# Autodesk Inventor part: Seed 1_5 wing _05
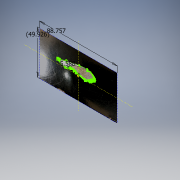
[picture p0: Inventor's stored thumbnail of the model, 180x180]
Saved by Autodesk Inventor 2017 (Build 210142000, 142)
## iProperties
Created: 2017-01
Part Number: Seed 1_5 wing _05
Material: Generic
Document SubType Name: Modeling
Designer: Brock Davis
Density: 1 g/cm^3
Appearance: Default
Author: Brock Davis
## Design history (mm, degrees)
sketch "Sketch1"
  geometry: L1 (-44.378, 24.963)-(44.378, 24.963); L2 (44.378, 24.963)-(44.378, -24.963); L3 (44.378, -24.963)-(-44.378, -24.963); L4 (-44.378, -24.963)-(-44.378, 24.963); L5 (0, 34.948)-(0, -34.948) reference; L6 (-62.13, 0)-(62.13, 0) reference; L7 (-14.664, 7.615)-(-12.849, 2.33); 50 further points; 1 other entity
  constraints: 2 end point, 67 other
  dimensions: "d12" = 5.588 distance of L7.start L7.end; "d21" = 88.7568 distance of L1.start L1.end; "d22" = 49.9257 distance of L3.end L1.start (derived)
extrude "Extrusion1" new body sketch "Sketch1" stored distance "d43" = 0.05; taper "d44" = 0 deg
sketch "Sketch2"
  geometry: L1 (-19.714, 6.093)-(-20.975, 5.834) reference; 20 further points
  constraints: 27 other
extrude "Extrusion2" join sketch "Sketch2" stored distance "d46" = 0.43; taper "d47" = 0 deg
sketch "Sketch3"
  geometry: L1 (-8.597, 8.182)-(-11.937, 8.182) reference; L2 (-19.714, 6.093)-(-20.975, 5.834) reference; 4 further points
  constraints: 5 other
extrude "Extrusion3" join sketch "Sketch3" stored distance "d48" = 1.5; taper "d49" = 0 deg
fillet "Fillet1" dims "d50" = 3.175
fillet "Fillet2" dims "d51" = 0.2
body "Solid1"
node "Image1"
node "Projected Loop1"
node "Projected Loop2"
